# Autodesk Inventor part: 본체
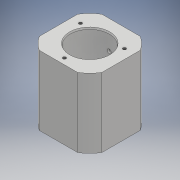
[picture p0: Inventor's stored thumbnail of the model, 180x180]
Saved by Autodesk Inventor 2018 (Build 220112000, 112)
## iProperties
Created: 2020-02
Part Number: 본체
Material: Generic
Document SubType Name: Modeling
Designer: Administrator
Density: 1 g/cm^3
Appearance: Default
Author: Administrator
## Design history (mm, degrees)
sketch "스케치1"
  geometry: L1 (-19.551, -32)-(19.551, -32); L2 (32, -19.551)-(32, 19.551); L3 (19.551, 32)-(-19.551, 32); L4 (-32, 19.551)-(-32, -19.551); L5 (-32, -32)-(32, 32); L6 (32, -32)-(-32, 32); A1 r 37.5 centre (0, 0) between (-19.551, 32) and (-32, 19.551); A2 r 37.5 centre (0, 0) between (-32, -19.551) and (-19.551, -32); A3 r 37.5 centre (0, 0) between (19.551, -32) and (32, -19.551); A4 r 37.5 centre (0, 0) between (32, 19.551) and (19.551, 32); 1 further point
  constraints: 12 end point, 8 point on circle, 4 centre point, 2 midpoint, 2 parallel, 2 perpendicular, 1 coincident, 1 horizontal
  dimensions: "d1" = 64 distance of L5.end L6.end; "d2" = 64 distance of L6.start L5.end; "d3" = 37.5 radius of A4; "d4" = 37.5 radius of A3; "d5" = 37.5 radius of A2; "d6" = 37.5 radius of A1; "d7" = 45 deg angle of L6 L2; "d8" = 64 distance between parallel lines of L2 L4; "d9" = 64 distance between parallel lines of L3 L1; "d10" = 32 distance from line of point (0, 0) L2; "d11" = 32 distance from line of point (0, 0) L3; "d12" = 0 distance from line of L5.end L2; "d13" = 64 distance from line of L5.start L2
extrude "돌출1" new body sketch "스케치1" distance "d14" = 71; taper "d15" = 0 deg
sketch "스케치2"
  geometry: C1 r 14 at (0, 0); 1 further point
  constraints: 1 centre point, 1 coincident
  dimensions: "d16" = 28 diameter of C1
extrude "돌출2" join sketch "스케치2" distance "d17" = 12; taper "d18" = 0 deg
sketch "스케치3"
  geometry: C1 r 20 at (0, 0); 1 further point
  constraints: 1 centre point, 1 coincident
  dimensions: "d19" = 40 diameter of C1
extrude "돌출3" cut sketch "스케치3" distance "d20" = 62; taper "d21" = 0 deg
sketch "스케치4"
  geometry: C1 r 2 at (0, 0); 1 further point
  constraints: 1 centre point, 1 coincident
  dimensions: "d22" = 4 diameter of C1
extrude "돌출4" cut sketch "스케치4" distance "d23" = 62; taper "d24" = 0 deg
sketch "스케치5"
  geometry: C1 r 2 at (0, 0) reference; 2 further points
  constraints: 1 coincident
hole "구멍1" sketch "스케치5" at (0, 0) diameter "d25" = 8.376; stored, may be unused: countersink angle "d29" = 90 deg, drill point angle "d31" = 118 deg; dims "d26" = 14, "d27" = 4, "d28" = 2, "d30" = 17
sketch "스케치6"
  geometry: L1 (39.102, -71)-(0, -71) reference; L2 (-12.449, 0)-(-12.449, -71) reference; C1 r 2 at (19.551, -54); 1 further point
  constraints: 1 centre point
  dimensions: "d32" = 17 distance from line of L1 C1.centre; "d33" = 32 distance from line of L2 C1.centre; "d34" = 4 diameter of C1
extrude "돌출5" cut sketch "스케치6" distance "d35" = 20; taper "d36" = 0 deg
sketch "스케치7"
  geometry: C1 r 2 at (19.551, -54) reference; 2 further points
  constraints: 1 coincident
hole "구멍2" sketch "스케치7" at (19.551, -54) diameter "d37" = 8.376; stored, may be unused: countersink angle "d41" = 90 deg, drill point angle "d43" = 118 deg; dims "d38" = 6, "d39" = 4, "d40" = 2, "d42" = 9
sketch "스케치8"
  geometry: C1 r 2 at (0, 0) reference; A1 r 26 centre (0, 0) between (0, 26) and (26, 0); 3 further points
  constraints: 4 point on circle, 1 centre point, 1 coincident
  dimensions: "d44" = 52 diameter of A1
hole "구멍3" sketch "스케치8" at (0, 26), (26, 0), (0, -26), (-26, 0) diameter "d45" = 3.242; stored, may be unused: countersink angle "d49" = 90 deg, drill point angle "d51" = 118 deg; dims "d46" = 10, "d47" = 4, "d48" = 2, "d50" = 12
sketch "스케치10"
  geometry: L1 (0, 26)-(0, -26); L2 (0, 0)-(22.517, 13); L3 (0, 0)-(-22.517, 13); C1 r 2 at (0, 0) reference; C2 r 1.621 at (0, 26) reference; C3 r 4.188 at (0, 0) reference; C4 r 14 at (0, 0) reference; A1 r 26 centre (0, 0) between (0, -26) and (-22.517, 13); 4 further points
  constraints: 6 end point, 4 coincident, 3 point on circle, 1 centre point, 1 vertical
  dimensions: "d66" = 52 diameter of A1; "d67" = 60 deg angle of L1 L2; "d68" = 60 deg angle of L1 L3
hole "구멍5" sketch "스케치10" at (-22.517, 13), (22.517, 13), (0, -26) diameter "d69" = 3.242; stored, may be unused: countersink angle "d73" = 90 deg, drill point angle "d75" = 118 deg; dims "d70" = 10, "d71" = 4, "d72" = 2, "d74" = 12
sketch "스케치11"
  geometry: L1 (20, 71)-(20, 9) reference; L2 (20, 71)-(20, 69.2); L3 (20, 69.2)-(20.482, 71); L4 (-20, 71)-(20, 71) reference; L5 (20, 71)-(20.482, 71); L6 (32, 71)-(19.551, 71) reference; L7 (0, 81.964)-(0, -65.316); 1 further point
  constraints: 8 end point, 3 point on line, 1 vertical
  dimensions: "d76" = 1.8 distance of L2.start L2.end; "d77" = 15 deg angle of L1 L3
revolve "회전1" sketch "스케치11" stored, may be unused: angle "d78" = 90 deg
chamfer "모따기1" distance "d79" = 1; stored, may be unused: second distance "d80" = 2, angle "d81" = 45 deg
sketch "스케치12"
  geometry: L1 (0, 0)-(39.102, 0) reference; 3 further points
  constraints: 1 midpoint, 1 vertical alignment, 1 other
  dimensions: "d82" = 20 distance from line of L1 point (19.551, -20)
feature "엠보싱1" sketch "스케치12" dims "d2" = 64, "d83" = 0.5, "d84" = 0
node "솔리드1"
other parameters: "d0" = 75
